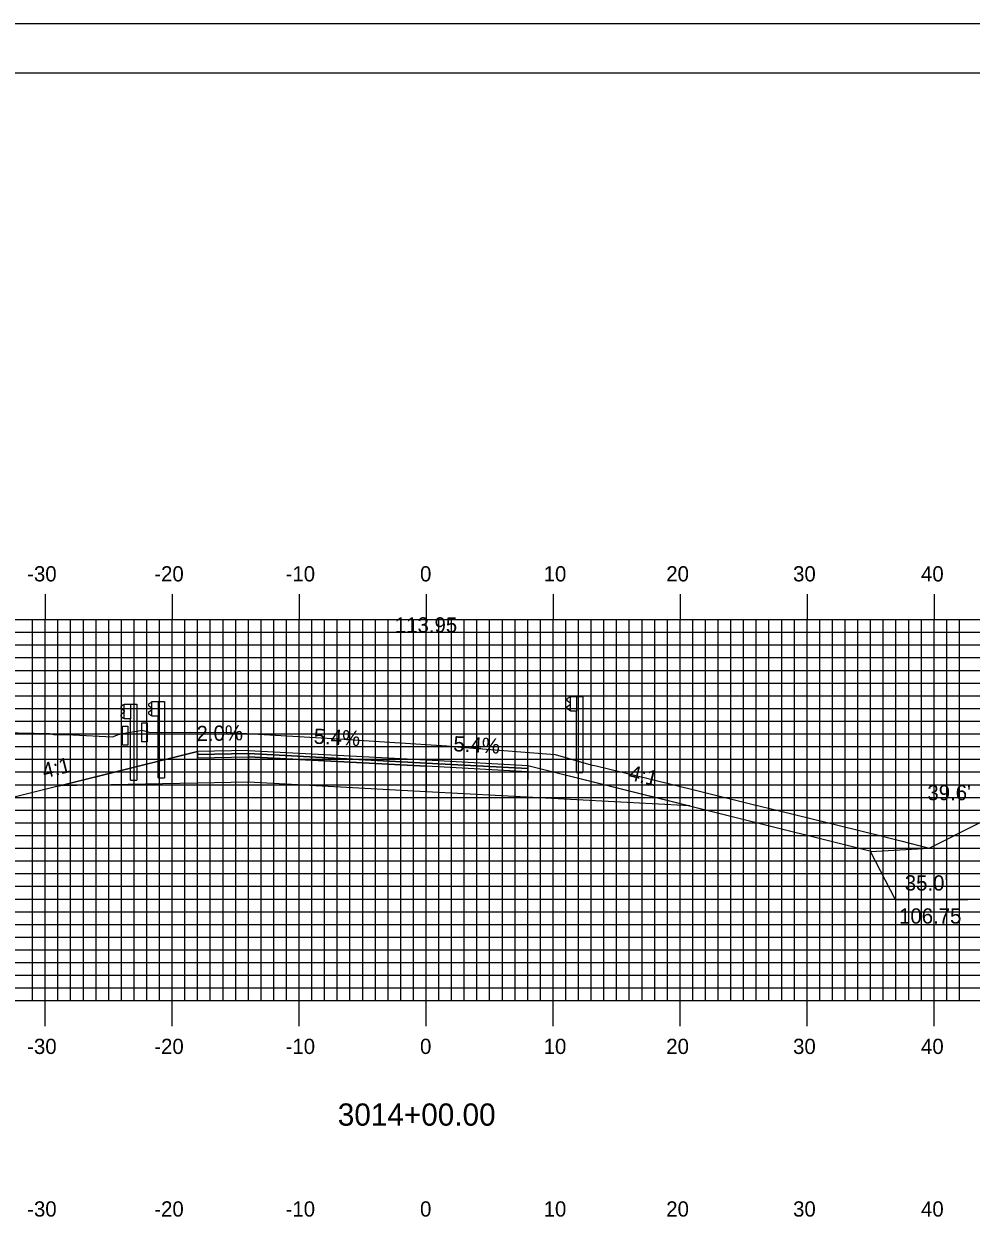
# Model space of a CAD drawing. Extents: x 1684405 to 1684749, y 461260 to 461480.
# Drawn here: x 1684539.5 to 1684614.1, y 461385.6 to 461480 of the extents above; entities that cross this region are included whole.
import ezdxf

# ---------------------------------------------------------------- set-up
doc = ezdxf.new("R2010")
doc.units = 0
for name, color, linetype in [('ANNOTATION', 7, 'Continuous'), ('BORDER', 7, 'Continuous'), ('D_Roadway_Centerline_Text', 7, 'Continuous'), ('D_Roadway_Edge_Shoulder', 7, 'Continuous'), ('D_Roadway_Edge_TW', 7, 'Continuous'), ('D_Roadway_Pavement', 7, 'Continuous'), ('D_Roadway_SlopeLines', 7, 'Continuous'), ('D_Roadway_SubGrade', 7, 'Continuous'), ('D_Text_Standard', 7, 'Continuous'), ('H_V ANNOTATION', 7, 'Continuous'), ('M_Guardrail', 7, 'Continuous'), ('M_Roadway_Centerline', 7, 'Continuous'), ('MAJOR', 7, 'Continuous'), ('MINOR', 7, 'Continuous'), ('PLOT BOUNDARY', 7, 'Continuous'), ('S_Curb_Type_1', 7, 'Continuous'), ('S_Guardrail_Beam', 7, 'Continuous'), ('S_Roadway_Centerline', 7, 'Continuous')]:
    doc.layers.add(name, color=color, linetype=linetype)

msp = doc.modelspace()

# ---------------------------------------------------------------- linework, layer by layer
at = {"layer": 'ANNOTATION'}
msp.add_lwpolyline([(1684613.854, 461411.01), (1684608.163, 461411.01), (1684606.203, 461414.822)], dxfattribs=at)
at = {"layer": 'BORDER'}
msp.add_lwpolyline([(1684421.603, 461266.072), (1684741.603, 461266.072), (1684741.603, 461476.072), (1684421.603, 461476.072)], close=True, dxfattribs=at)
at = {"layer": 'D_Roadway_Edge_Shoulder'}
for points in [[(1684557.203, 461422.774), (1684553.203, 461422.694), (1684553.203, 461422.444), (1684557.203, 461422.524)], [(1684557.203, 461422.524), (1684553.203, 461422.444), (1684553.203, 461422.194), (1684557.203, 461422.274)], [(1684571.203, 461422.018), (1684579.203, 461421.586), (1684579.203, 461421.336), (1684571.203, 461421.768)]]:
    msp.add_lwpolyline(points, close=True, dxfattribs=at)
at = {"layer": 'D_Roadway_Edge_TW'}
msp.add_lwpolyline([(1684557.203, 461422.774), (1684571.203, 461422.018), (1684571.203, 461421.768), (1684557.203, 461422.524)], close=True, dxfattribs=at)
at = {"layer": 'D_Roadway_Pavement'}
for points in [[(1684557.203, 461422.524), (1684571.203, 461421.768), (1684571.203, 461421.518), (1684557.203, 461422.274)], [(1684571.203, 461421.768), (1684579.203, 461421.336), (1684579.203, 461421.072), (1684571.203, 461421.518)]]:
    msp.add_lwpolyline(points, close=True, dxfattribs=at)
for points in [[(1684557.203, 461422.524), (1684557.203, 461422.274)], [(1684557.203, 461422.524), (1684557.203, 461422.274)], [(1684557.203, 461422.524), (1684557.203, 461422.274)], [(1684571.203, 461421.768), (1684571.203, 461421.518)], [(1684571.203, 461421.768), (1684571.203, 461421.518)], [(1684571.203, 461421.768), (1684571.203, 461421.518)]]:
    msp.add_lwpolyline(points, dxfattribs=at)
at = {"layer": 'D_Roadway_SlopeLines'}
msp.add_line((1684606.203, 461414.822), (1684610.813, 461415.085), dxfattribs=at)
for points in [[(1684553.203, 461422.694), (1684538.334, 461418.977)], [(1684579.203, 461421.586), (1684583.203, 461420.586), (1684606.25, 461414.825)]]:
    msp.add_lwpolyline(points, dxfattribs=at)
at = {"layer": 'D_Roadway_SubGrade'}
for points in [[(1684557.203, 461420.274), (1684542.334, 461419.977), (1684553.203, 461422.694), (1684553.203, 461422.444), (1684557.203, 461422.524), (1684557.203, 461422.274)], [(1684557.203, 461422.274), (1684571.203, 461421.518), (1684571.203, 461419.518), (1684557.203, 461420.274)], [(1684571.203, 461421.518), (1684571.203, 461421.768), (1684579.203, 461421.336), (1684579.203, 461421.586), (1684591.958, 461418.398), (1684571.203, 461419.518)]]:
    msp.add_lwpolyline(points, close=True, dxfattribs=at)
at = {"layer": 'M_Guardrail'}
for p, q in [((1684582.462, 461426.932), (1684582.319, 461426.832)), ((1684582.319, 461426.689), (1684582.514, 461426.553)), ((1684582.514, 461426.333), (1684582.319, 461426.197)), ((1684582.561, 461426.953), (1684582.479, 461426.939)), ((1684582.548, 461426.489), (1684582.548, 461426.398)), ((1684582.561, 461427.026), (1684583.051, 461427.026)), ((1684582.561, 461425.86), (1684582.561, 461427.026)), ((1684583.051, 461427.026), (1684583.542, 461427.026)), ((1684583.051, 461427.026), (1684583.051, 461425.86)), ((1684583.542, 461427.026), (1684583.542, 461421.026)), ((1684582.319, 461426.054), (1684582.462, 461425.954)), ((1684582.479, 461425.947), (1684582.561, 461425.933)), ((1684583.051, 461425.86), (1684582.561, 461425.86)), ((1684583.051, 461421.026), (1684583.051, 461425.86)), ((1684583.051, 461421.026), (1684583.542, 461421.026))]:
    msp.add_line(p, q, dxfattribs=at)
for centre, major_axis, start_param, end_param in [((1684582.369, 461426.761), (-0.0877, 0), 5.323254, 7.243116), ((1684582.486, 461426.898), (-0.0417, 0), 4.886922, 5.323254), ((1684582.469, 461426.489), (0.0789, 0), 0, 0.959931), ((1684582.469, 461426.398), (0.0789, 0), 5.323254, 6.283185), ((1684582.369, 461426.125), (-0.0877, 0), 5.323254, 7.243116), ((1684582.486, 461425.988), (-0.0417, 0), 0.959931, 1.396263)]:
    msp.add_ellipse(centre, major_axis=major_axis, ratio=0.995501, start_param=start_param, end_param=end_param, dxfattribs=at)
at = {"layer": 'MAJOR'}
for p, q in [((1684541.203, 461435.076), (1684541.203, 461433.072)), ((1684551.203, 461435.076), (1684551.203, 461433.072)), ((1684561.203, 461435.076), (1684561.203, 461433.072)), ((1684571.203, 461435.076), (1684571.203, 461433.072)), ((1684581.203, 461435.076), (1684581.203, 461433.072)), ((1684591.203, 461435.076), (1684591.203, 461433.072)), ((1684601.203, 461435.076), (1684601.203, 461433.072)), ((1684611.203, 461435.076), (1684611.203, 461433.072)), ((1684431.203, 461433.072), (1684711.203, 461433.072)), ((1684431.203, 461433.072), (1684711.203, 461433.072)), ((1684541.203, 461403.072), (1684541.203, 461433.072)), ((1684551.203, 461403.072), (1684551.203, 461433.072)), ((1684561.203, 461403.072), (1684561.203, 461433.072)), ((1684571.203, 461403.072), (1684571.203, 461433.072)), ((1684581.203, 461403.072), (1684581.203, 461433.072)), ((1684591.203, 461403.072), (1684591.203, 461433.072)), ((1684601.203, 461403.072), (1684601.203, 461433.072)), ((1684611.203, 461403.072), (1684611.203, 461433.072)), ((1684431.203, 461428.072), (1684711.203, 461428.072)), ((1684431.203, 461423.072), (1684711.203, 461423.072)), ((1684431.203, 461418.072), (1684711.203, 461418.072)), ((1684431.203, 461413.072), (1684711.203, 461413.072)), ((1684431.203, 461408.072), (1684711.203, 461408.072)), ((1684431.203, 461403.072), (1684711.203, 461403.072)), ((1684431.203, 461403.072), (1684711.203, 461403.072)), ((1684541.203, 461401.068), (1684541.203, 461403.072)), ((1684551.203, 461401.068), (1684551.203, 461403.072)), ((1684561.203, 461401.068), (1684561.203, 461403.072)), ((1684571.203, 461401.068), (1684571.203, 461403.072)), ((1684581.203, 461401.068), (1684581.203, 461403.072)), ((1684591.203, 461401.068), (1684591.203, 461403.072)), ((1684601.203, 461401.068), (1684601.203, 461403.072)), ((1684611.203, 461401.068), (1684611.203, 461403.072))]:
    msp.add_line(p, q, dxfattribs=at)
at = {"layer": 'MINOR'}
for p, q in [((1684540.203, 461403.072), (1684540.203, 461433.072)), ((1684542.203, 461403.072), (1684542.203, 461433.072)), ((1684543.203, 461403.072), (1684543.203, 461433.072)), ((1684544.203, 461403.072), (1684544.203, 461433.072)), ((1684545.203, 461403.072), (1684545.203, 461433.072)), ((1684546.203, 461403.072), (1684546.203, 461433.072)), ((1684547.203, 461403.072), (1684547.203, 461433.072)), ((1684548.203, 461403.072), (1684548.203, 461433.072)), ((1684549.203, 461403.072), (1684549.203, 461433.072)), ((1684550.203, 461403.072), (1684550.203, 461433.072)), ((1684552.203, 461403.072), (1684552.203, 461433.072)), ((1684553.203, 461403.072), (1684553.203, 461433.072)), ((1684554.203, 461403.072), (1684554.203, 461433.072)), ((1684555.203, 461403.072), (1684555.203, 461433.072)), ((1684556.203, 461403.072), (1684556.203, 461433.072)), ((1684557.203, 461403.072), (1684557.203, 461433.072)), ((1684558.203, 461403.072), (1684558.203, 461433.072)), ((1684559.203, 461403.072), (1684559.203, 461433.072)), ((1684560.203, 461403.072), (1684560.203, 461433.072)), ((1684562.203, 461403.072), (1684562.203, 461433.072)), ((1684563.203, 461403.072), (1684563.203, 461433.072)), ((1684564.203, 461403.072), (1684564.203, 461433.072)), ((1684565.203, 461403.072), (1684565.203, 461433.072)), ((1684566.203, 461403.072), (1684566.203, 461433.072)), ((1684567.203, 461403.072), (1684567.203, 461433.072)), ((1684568.203, 461403.072), (1684568.203, 461433.072)), ((1684569.203, 461403.072), (1684569.203, 461433.072)), ((1684570.203, 461403.072), (1684570.203, 461433.072)), ((1684572.203, 461403.072), (1684572.203, 461433.072)), ((1684573.203, 461403.072), (1684573.203, 461433.072)), ((1684574.203, 461403.072), (1684574.203, 461433.072)), ((1684575.203, 461403.072), (1684575.203, 461433.072)), ((1684576.203, 461403.072), (1684576.203, 461433.072)), ((1684577.203, 461403.072), (1684577.203, 461433.072)), ((1684578.203, 461403.072), (1684578.203, 461433.072)), ((1684579.203, 461403.072), (1684579.203, 461433.072)), ((1684580.203, 461403.072), (1684580.203, 461433.072)), ((1684582.203, 461403.072), (1684582.203, 461433.072)), ((1684583.203, 461403.072), (1684583.203, 461433.072)), ((1684584.203, 461403.072), (1684584.203, 461433.072)), ((1684585.203, 461403.072), (1684585.203, 461433.072)), ((1684586.203, 461403.072), (1684586.203, 461433.072)), ((1684587.203, 461403.072), (1684587.203, 461433.072)), ((1684588.203, 461403.072), (1684588.203, 461433.072)), ((1684589.203, 461403.072), (1684589.203, 461433.072)), ((1684590.203, 461403.072), (1684590.203, 461433.072)), ((1684592.203, 461403.072), (1684592.203, 461433.072)), ((1684593.203, 461403.072), (1684593.203, 461433.072)), ((1684594.203, 461403.072), (1684594.203, 461433.072)), ((1684595.203, 461403.072), (1684595.203, 461433.072)), ((1684596.203, 461403.072), (1684596.203, 461433.072)), ((1684597.203, 461403.072), (1684597.203, 461433.072)), ((1684598.203, 461403.072), (1684598.203, 461433.072)), ((1684599.203, 461403.072), (1684599.203, 461433.072)), ((1684600.203, 461403.072), (1684600.203, 461433.072)), ((1684602.203, 461403.072), (1684602.203, 461433.072)), ((1684603.203, 461403.072), (1684603.203, 461433.072)), ((1684604.203, 461403.072), (1684604.203, 461433.072)), ((1684605.203, 461403.072), (1684605.203, 461433.072)), ((1684606.203, 461403.072), (1684606.203, 461433.072)), ((1684607.203, 461403.072), (1684607.203, 461433.072)), ((1684608.203, 461403.072), (1684608.203, 461433.072)), ((1684609.203, 461403.072), (1684609.203, 461433.072)), ((1684610.203, 461403.072), (1684610.203, 461433.072)), ((1684612.203, 461403.072), (1684612.203, 461433.072)), ((1684613.203, 461403.072), (1684613.203, 461433.072)), ((1684431.203, 461432.072), (1684711.203, 461432.072)), ((1684431.203, 461431.072), (1684711.203, 461431.072)), ((1684431.203, 461430.072), (1684711.203, 461430.072)), ((1684431.203, 461429.072), (1684711.203, 461429.072)), ((1684431.203, 461427.072), (1684711.203, 461427.072)), ((1684431.203, 461426.072), (1684711.203, 461426.072)), ((1684431.203, 461425.072), (1684711.203, 461425.072)), ((1684431.203, 461424.072), (1684711.203, 461424.072)), ((1684431.203, 461422.072), (1684711.203, 461422.072)), ((1684431.203, 461421.072), (1684711.203, 461421.072)), ((1684579.203, 461421.586), (1684579.203, 461420.491)), ((1684431.203, 461420.072), (1684711.203, 461420.072)), ((1684431.203, 461419.072), (1684711.203, 461419.072)), ((1684431.203, 461417.072), (1684711.203, 461417.072)), ((1684431.203, 461416.072), (1684711.203, 461416.072)), ((1684431.203, 461415.072), (1684711.203, 461415.072)), ((1684431.203, 461414.072), (1684711.203, 461414.072)), ((1684431.203, 461412.072), (1684711.203, 461412.072)), ((1684431.203, 461411.072), (1684711.203, 461411.072)), ((1684431.203, 461410.072), (1684711.203, 461410.072)), ((1684431.203, 461409.072), (1684711.203, 461409.072)), ((1684431.203, 461407.072), (1684711.203, 461407.072)), ((1684431.203, 461406.072), (1684711.203, 461406.072)), ((1684431.203, 461405.072), (1684711.203, 461405.072)), ((1684431.203, 461404.072), (1684711.203, 461404.072))]:
    msp.add_line(p, q, dxfattribs=at)
at = {"layer": 'PLOT BOUNDARY'}
msp.add_lwpolyline([(1684405.417, 461259.954), (1684745.417, 461259.954), (1684745.417, 461479.954), (1684405.417, 461479.954)], close=True, dxfattribs=at)
at = {"layer": 'S_Curb_Type_1'}
for points in [[(1684547.3, 461424.689), (1684547.716, 461424.689), (1684547.716, 461423.189), (1684547.3, 461423.189)], [(1684547.3, 461424.689), (1684547.716, 461424.689), (1684547.716, 461423.189), (1684547.3, 461423.189)], [(1684548.819, 461424.952), (1684549.236, 461424.952), (1684549.236, 461423.452), (1684548.819, 461423.452)], [(1684548.819, 461424.952), (1684549.236, 461424.952), (1684549.236, 461423.452), (1684548.819, 461423.452)]]:
    msp.add_lwpolyline(points, close=True, dxfattribs=at)
at = {"layer": 'S_Guardrail_Beam'}
for p, q in [((1684547.324, 461426.322), (1684547.181, 461426.222)), ((1684547.324, 461426.322), (1684547.181, 461426.222)), ((1684547.423, 461426.343), (1684547.341, 461426.329)), ((1684547.423, 461426.343), (1684547.341, 461426.329)), ((1684547.423, 461426.416), (1684547.913, 461426.416)), ((1684547.423, 461425.25), (1684547.423, 461426.416)), ((1684547.423, 461426.416), (1684547.913, 461426.416)), ((1684547.423, 461425.25), (1684547.423, 461426.416)), ((1684547.913, 461426.416), (1684548.404, 461426.416)), ((1684547.913, 461426.416), (1684547.913, 461425.25)), ((1684547.913, 461426.416), (1684548.404, 461426.416)), ((1684547.913, 461426.416), (1684547.913, 461425.25)), ((1684548.404, 461426.416), (1684548.404, 461420.416)), ((1684548.404, 461426.416), (1684548.404, 461420.416)), ((1684549.508, 461426.527), (1684549.365, 461426.427)), ((1684549.508, 461426.527), (1684549.365, 461426.427)), ((1684549.607, 461426.548), (1684549.525, 461426.534)), ((1684549.607, 461426.548), (1684549.525, 461426.534)), ((1684549.607, 461426.621), (1684550.097, 461426.621)), ((1684549.607, 461425.454), (1684549.607, 461426.621)), ((1684549.607, 461426.621), (1684550.097, 461426.621)), ((1684549.607, 461425.454), (1684549.607, 461426.621)), ((1684550.097, 461426.621), (1684550.588, 461426.621)), ((1684550.097, 461426.621), (1684550.097, 461425.454)), ((1684550.097, 461426.621), (1684550.588, 461426.621)), ((1684550.097, 461426.621), (1684550.097, 461425.454)), ((1684550.588, 461426.621), (1684550.588, 461420.621)), ((1684550.588, 461426.621), (1684550.588, 461420.621)), ((1684547.181, 461426.079), (1684547.376, 461425.943)), ((1684547.181, 461426.079), (1684547.376, 461425.943)), ((1684547.376, 461425.723), (1684547.181, 461425.587)), ((1684547.376, 461425.723), (1684547.181, 461425.587)), ((1684547.181, 461425.444), (1684547.324, 461425.344)), ((1684547.181, 461425.444), (1684547.324, 461425.344)), ((1684547.41, 461425.879), (1684547.41, 461425.787)), ((1684547.41, 461425.879), (1684547.41, 461425.787)), ((1684549.365, 461426.284), (1684549.56, 461426.148)), ((1684549.365, 461426.284), (1684549.56, 461426.148)), ((1684549.56, 461425.928), (1684549.365, 461425.792)), ((1684549.56, 461425.928), (1684549.365, 461425.792)), ((1684549.365, 461425.649), (1684549.508, 461425.549)), ((1684549.365, 461425.649), (1684549.508, 461425.549)), ((1684549.525, 461425.542), (1684549.607, 461425.527)), ((1684549.525, 461425.542), (1684549.607, 461425.527)), ((1684549.594, 461426.083), (1684549.594, 461425.992)), ((1684549.594, 461426.083), (1684549.594, 461425.992)), ((1684550.097, 461425.454), (1684549.607, 461425.454)), ((1684550.097, 461425.454), (1684549.607, 461425.454)), ((1684550.097, 461420.621), (1684550.097, 461425.454)), ((1684550.097, 461420.621), (1684550.097, 461425.454)), ((1684547.341, 461425.337), (1684547.423, 461425.323)), ((1684547.341, 461425.337), (1684547.423, 461425.323)), ((1684547.913, 461425.25), (1684547.423, 461425.25)), ((1684547.913, 461425.25), (1684547.423, 461425.25)), ((1684547.913, 461420.416), (1684547.913, 461425.25)), ((1684547.913, 461420.416), (1684547.913, 461425.25)), ((1684547.913, 461420.416), (1684548.404, 461420.416)), ((1684547.913, 461420.416), (1684548.404, 461420.416)), ((1684550.097, 461420.621), (1684550.588, 461420.621)), ((1684550.097, 461420.621), (1684550.588, 461420.621))]:
    msp.add_line(p, q, dxfattribs=at)
for centre, major_axis, start_param, end_param in [((1684547.348, 461426.288), (-0.0417, 0), 4.886922, 5.323254), ((1684547.348, 461426.288), (-0.0417, 0), 4.886922, 5.323254), ((1684549.415, 461426.355), (-0.0877, 0), 5.323254, 7.243116), ((1684549.415, 461426.355), (-0.0877, 0), 5.323254, 7.243116), ((1684549.532, 461426.493), (-0.0417, 0), 4.886922, 5.323254), ((1684549.532, 461426.493), (-0.0417, 0), 4.886922, 5.323254), ((1684547.231, 461426.151), (-0.0877, 0), 5.323254, 7.243116), ((1684547.231, 461426.151), (-0.0877, 0), 5.323254, 7.243116), ((1684547.231, 461425.515), (-0.0877, 0), 5.323254, 7.243116), ((1684547.231, 461425.515), (-0.0877, 0), 5.323254, 7.243116), ((1684547.331, 461425.879), (0.0789, 0), 0, 0.959931), ((1684547.331, 461425.879), (0.0789, 0), 0, 0.959931), ((1684547.331, 461425.787), (0.0789, 0), 5.323254, 6.283185), ((1684547.331, 461425.787), (0.0789, 0), 5.323254, 6.283185), ((1684549.415, 461425.72), (-0.0877, 0), 5.323254, 7.243116), ((1684549.415, 461425.72), (-0.0877, 0), 5.323254, 7.243116), ((1684549.532, 461425.583), (-0.0417, 0), 0.959931, 1.396263), ((1684549.532, 461425.583), (-0.0417, 0), 0.959931, 1.396263), ((1684549.515, 461426.083), (0.0789, 0), 0, 0.959931), ((1684549.515, 461426.083), (0.0789, 0), 0, 0.959931), ((1684549.515, 461425.992), (0.0789, 0), 5.323254, 6.283185), ((1684549.515, 461425.992), (0.0789, 0), 5.323254, 6.283185), ((1684547.348, 461425.378), (-0.0417, 0), 0.959931, 1.396263), ((1684547.348, 461425.378), (-0.0417, 0), 0.959931, 1.396263)]:
    msp.add_ellipse(centre, major_axis=major_axis, ratio=0.995501, start_param=start_param, end_param=end_param, dxfattribs=at)
at = {"layer": 'S_Roadway_Centerline'}
for points in [[(1684537.826, 461424.176), (1684541.556, 461424.091), (1684541.883, 461424.021), (1684543.377, 461423.986), (1684546.501, 461423.836), (1684546.975, 461424.024), (1684547.3, 461424.106), (1684548.557, 461424.301), (1684548.819, 461424.369), (1684549.241, 461424.247), (1684549.361, 461424.213), (1684550.369, 461424.189), (1684552.616, 461424.195), (1684555.74, 461424.179), (1684564.744, 461423.65), (1684564.921, 461423.636), (1684565.09, 461423.629), (1684565.113, 461423.627), (1684565.476, 461423.605), (1684572.823, 461423.134), (1684573.943, 461423.014), (1684574.622, 461422.96), (1684581.375, 461422.438)], [(1684581.375, 461422.438), (1684584.162, 461421.641), (1684584.587, 461421.559), (1684588.793, 461420.526), (1684592.738, 461419.558), (1684596.85, 461418.549), (1684599.042, 461418.01), (1684602.784, 461417.092), (1684606.27, 461416.236), (1684606.293, 461416.23), (1684606.31, 461416.226), (1684608.377, 461415.702), (1684608.576, 461415.664), (1684610.813, 461415.085), (1684614.839, 461417.087), (1684615.662, 461417.434), (1684615.746, 461417.47), (1684615.849, 461417.513), (1684616.308, 461417.708), (1684617.165, 461418.072), (1684621.799, 461420.034), (1684622.554, 461420.357)]]:
    msp.add_lwpolyline(points, dxfattribs=at)

# ---------------------------------------------------------------- texts
at = {"layer": 'ANNOTATION'}
for s, rotation, p in [('2.0%', 1.14576, (1684553.13, 461423.493)), ('5.4%', 356.90903, (1684562.323, 461423.301)), ('5.4%', 356.90903, (1684573.323, 461422.707)), ('4:1', 14.03624, (1684541.129, 461420.556)), ('4:1', 345.96376, (1684587.087, 461420.477))]:
    msp.add_text(s, height=1.2, rotation=rotation, dxfattribs=at).set_placement(p)
for s, p in [("35.0' ", (1684608.897, 461411.736)), ('106.75', (1684608.448, 461409.136))]:
    msp.add_text(s, height=1.2, dxfattribs=at).set_placement(p)
at = {"layer": 'D_Roadway_Centerline_Text'}
msp.add_text('113.95', height=1.2, dxfattribs=at).set_placement((1684568.737, 461432.048))
at = {"layer": 'D_Text_Standard'}
msp.add_text("39.6'", height=1.2, dxfattribs=at).set_placement((1684610.677, 461418.85))
at = {"layer": 'H_V ANNOTATION'}
for s, height, p in [('-30', 1.2, (1684539.78, 461436.072)), ('-20', 1.2, (1684549.79, 461436.072)), ('-10', 1.2, (1684560.133, 461436.072)), ('0', 1.2, (1684570.721, 461436.072)), ('10', 1.2, (1684580.454, 461436.072)), ('20', 1.2, (1684590.111, 461436.072)), ('30', 1.2, (1684600.101, 461436.072)), ('40', 1.2, (1684610.176, 461436.072)), ('-30', 1.2, (1684539.78, 461398.872)), ('-20', 1.2, (1684549.79, 461398.872)), ('-10', 1.2, (1684560.133, 461398.872)), ('0', 1.2, (1684570.721, 461398.872)), ('10', 1.2, (1684580.454, 461398.872)), ('20', 1.2, (1684590.111, 461398.872)), ('30', 1.2, (1684600.101, 461398.872)), ('40', 1.2, (1684610.176, 461398.872)), ('3014+00.00', 1.75, (1684564.243, 461393.228)), ('-30', 1.2, (1684539.78, 461386.072)), ('-20', 1.2, (1684549.79, 461386.072)), ('-10', 1.2, (1684560.133, 461386.072)), ('0', 1.2, (1684570.721, 461386.072)), ('10', 1.2, (1684580.454, 461386.072)), ('20', 1.2, (1684590.111, 461386.072)), ('30', 1.2, (1684600.101, 461386.072)), ('40', 1.2, (1684610.176, 461386.072))]:
    msp.add_text(s, height=height, dxfattribs=at).set_placement(p)
at = {"layer": 'M_Roadway_Centerline'}
for s, p in [('C', (1684565.085, 461423.629)), ('L', (1684565.09, 461423.622))]:
    msp.add_text(s, height=0.0146, dxfattribs=at).set_placement(p)

doc.saveas('drawing.dxf')
